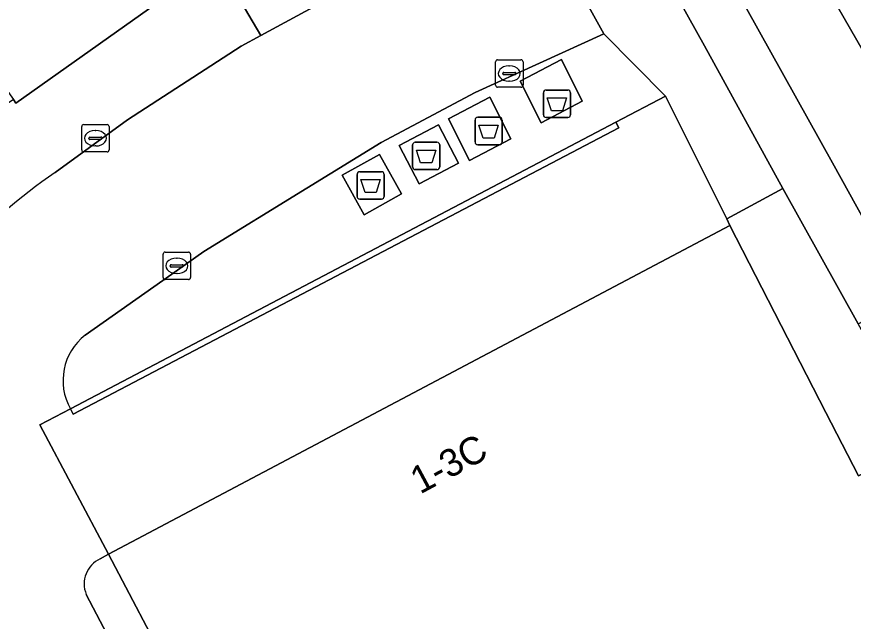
# Model space of a CAD drawing. Extents: x 161838 to 162344, y 381620 to 382160.
# Drawn here: x 162027.79 to 162058.3, y 381957.42 to 381979.46 of the extents above; entities that cross this region are included whole.
import ezdxf

# ---------------------------------------------------------------- set-up
doc = ezdxf.new("R2010")
doc.units = 0
for name, color, linetype in [('IMGEO_Afval_apart_plaats', 7, 'Continuous'), ('IMGEO_Erf', 7, 'Continuous'), ('IMGEO_Kolk', 7, 'Continuous'), ('IMGEO_Pand', 7, 'Continuous'), ('IMGEO_Pand_nummerreeks', 7, 'Continuous'), ('IMGEO_Pand_overbouw', 7, 'Continuous'), ('IMGEO_Parkeervlak_open', 7, 'Continuous'), ('IMGEO_Rijbaan_lokaal_gesloten', 7, 'Continuous'), ('IMGEO_Rijbaan_lokaal_open', 7, 'Continuous'), ('IMGEO_Voetpad_gesloten', 7, 'Continuous'), ('IMGEO_Voetpad_open', 7, 'Continuous')]:
    doc.layers.add(name, color=color, linetype=linetype)

msp = doc.modelspace()

# ---------------------------------------------------------------- linework, layer by layer
at = {"layer": 'IMGEO_Afval_apart_plaats'}
for p, q in [((162046.998, 381975.889), (162046.998, 381976.689)), ((162046.998, 381976.689), (162046.998, 381975.889)), ((162047.098, 381976.789), (162047.888, 381976.789)), ((162047.888, 381976.789), (162047.098, 381976.789)), ((162047.988, 381976.689), (162047.988, 381975.889)), ((162047.988, 381975.889), (162047.988, 381976.689)), ((162044.606, 381975.797), (162045.396, 381975.797)), ((162045.396, 381975.797), (162044.606, 381975.797)), ((162047.888, 381975.789), (162047.098, 381975.789)), ((162047.098, 381975.789), (162047.888, 381975.789)), ((162044.506, 381974.897), (162044.506, 381975.697)), ((162044.506, 381975.697), (162044.506, 381974.897)), ((162045.496, 381975.697), (162045.496, 381974.897)), ((162045.496, 381974.897), (162045.496, 381975.697)), ((162042.328, 381974.887), (162043.118, 381974.887)), ((162043.118, 381974.887), (162042.328, 381974.887)), ((162042.228, 381973.987), (162042.228, 381974.787)), ((162042.228, 381974.787), (162042.228, 381973.987)), ((162043.218, 381974.787), (162043.218, 381973.987)), ((162043.218, 381973.987), (162043.218, 381974.787)), ((162045.396, 381974.797), (162044.606, 381974.797)), ((162044.606, 381974.797), (162045.396, 381974.797)), ((162040.201, 381972.913), (162040.201, 381973.713)), ((162040.201, 381973.713), (162040.201, 381972.913)), ((162040.301, 381973.813), (162041.091, 381973.813)), ((162041.091, 381973.813), (162040.301, 381973.813)), ((162041.191, 381973.713), (162041.191, 381972.913)), ((162041.191, 381972.913), (162041.191, 381973.713)), ((162043.118, 381973.887), (162042.328, 381973.887)), ((162042.328, 381973.887), (162043.118, 381973.887)), ((162041.091, 381972.813), (162040.301, 381972.813)), ((162040.301, 381972.813), (162041.091, 381972.813))]:
    msp.add_line(p, q, dxfattribs=at)
for points in [[(162047.141, 381976.503), (162047.845, 381976.503), (162047.696, 381976.033), (162047.29, 381976.033), (162047.141, 381976.503)], [(162044.649, 381975.511), (162045.353, 381975.511), (162045.204, 381975.041), (162044.798, 381975.041), (162044.649, 381975.511)], [(162042.371, 381974.601), (162043.075, 381974.601), (162042.926, 381974.131), (162042.52, 381974.131), (162042.371, 381974.601)], [(162040.344, 381973.527), (162041.048, 381973.527), (162040.899, 381973.057), (162040.493, 381973.057), (162040.344, 381973.527)]]:
    msp.add_lwpolyline(points, dxfattribs=at)
for centre, start, end in [((162047.098, 381976.689), 90, 180), ((162047.098, 381976.689), 90, 180), ((162047.888, 381976.689), 0, 90), ((162047.888, 381976.689), 360, 90), ((162044.606, 381975.697), 90, 180), ((162044.606, 381975.697), 90, 180), ((162045.396, 381975.697), 0, 90), ((162045.396, 381975.697), 360, 90), ((162047.098, 381975.889), 180, 270), ((162047.098, 381975.889), 180, 270), ((162047.888, 381975.889), 270, 0), ((162047.888, 381975.889), 270, 0), ((162042.328, 381974.787), 90, 180), ((162042.328, 381974.787), 90, 180), ((162043.118, 381974.787), 0, 90), ((162043.118, 381974.787), 360, 90), ((162044.606, 381974.897), 180, 270), ((162044.606, 381974.897), 180, 270), ((162045.396, 381974.897), 270, 0), ((162045.396, 381974.897), 270, 0), ((162042.328, 381973.987), 180, 270), ((162042.328, 381973.987), 180, 270), ((162043.118, 381973.987), 270, 0), ((162043.118, 381973.987), 270, 0), ((162040.301, 381973.713), 90, 180), ((162040.301, 381973.713), 90, 180), ((162041.091, 381973.713), 0, 90), ((162041.091, 381973.713), 360, 90), ((162040.301, 381972.913), 180, 270), ((162040.301, 381972.913), 180, 270), ((162041.091, 381972.913), 270, 0), ((162041.091, 381972.913), 270, 0)]:
    msp.add_arc(centre, 0.1, start, end, dxfattribs=at)
at = {"layer": 'IMGEO_Erf'}
msp.add_lwpolyline([(162053.805, 381971.851), (162053.684, 381972.093), (162051.451, 381976.567), (162049.641, 381975.615), (162049.748, 381975.411), (162029.848, 381964.977), (162029.747, 381965.17), (162028.637, 381964.588), (162031.141, 381959.872)], close=True, dxfattribs=at)
at = {"layer": 'IMGEO_Kolk'}
for p, q in [((162045.33, 381977.892), (162046.182, 381977.892)), ((162045.255, 381976.966), (162045.255, 381977.818)), ((162045.743, 381977.672), (162045.768, 381977.672)), ((162046.256, 381977.818), (162046.256, 381976.966)), ((162045.514, 381977.386), (162045.514, 381977.398)), ((162045.952, 381977.349), (162045.554, 381977.349)), ((162045.557, 381977.435), (162045.955, 381977.435)), ((162045.998, 381977.398), (162045.998, 381977.386)), ((162045.766, 381977.112), (162045.741, 381977.112)), ((162046.182, 381976.892), (162045.33, 381976.892)), ((162030.159, 381974.606), (162030.159, 381975.458)), ((162030.234, 381975.532), (162031.086, 381975.532)), ((162031.16, 381975.458), (162031.16, 381974.606)), ((162030.647, 381975.312), (162030.672, 381975.312)), ((162030.418, 381975.026), (162030.418, 381975.038)), ((162030.856, 381974.989), (162030.458, 381974.989)), ((162030.461, 381975.075), (162030.859, 381975.075)), ((162030.902, 381975.038), (162030.902, 381975.026)), ((162030.67, 381974.752), (162030.645, 381974.752)), ((162031.086, 381974.532), (162030.234, 381974.532)), ((162033.202, 381970.879), (162034.054, 381970.879)), ((162033.127, 381969.953), (162033.127, 381970.805)), ((162033.615, 381970.659), (162033.64, 381970.659)), ((162034.128, 381970.805), (162034.128, 381969.953)), ((162033.386, 381970.373), (162033.386, 381970.385)), ((162033.824, 381970.336), (162033.426, 381970.336)), ((162033.429, 381970.422), (162033.827, 381970.422)), ((162033.87, 381970.385), (162033.87, 381970.373)), ((162033.638, 381970.099), (162033.613, 381970.099)), ((162034.054, 381969.879), (162033.202, 381969.879))]:
    msp.add_line(p, q, dxfattribs=at)
for points in [[(162045.33, 381977.892), (162046.182, 381977.892)], [(162045.255, 381976.966), (162045.255, 381977.818)], [(162046.256, 381977.818), (162046.256, 381976.966)], [(162046.182, 381976.892), (162045.33, 381976.892)], [(162030.159, 381974.606), (162030.159, 381975.458)], [(162030.234, 381975.532), (162031.086, 381975.532)], [(162031.16, 381975.458), (162031.16, 381974.606)], [(162031.086, 381974.532), (162030.234, 381974.532)], [(162033.202, 381970.879), (162034.054, 381970.879)], [(162033.127, 381969.953), (162033.127, 381970.805)], [(162034.128, 381970.805), (162034.128, 381969.953)], [(162034.054, 381969.879), (162033.202, 381969.879)]]:
    msp.add_lwpolyline(points, dxfattribs=at)
for centre, radius, start, end in [((162045.332, 381977.816), 0.0765, 91.552, 178.448), ((162045.332, 381977.816), 0.0765, 91.552, 178.448), ((162046.18, 381977.816), 0.0765, 1.552, 88.448), ((162046.18, 381977.816), 0.0765, 1.552, 88.448), ((162045.554, 381977.395), 0.0403, 85.8775, 175.7526), ((162045.551, 381977.385), 0.0366, 178.938, 274.7102), ((162045.955, 381977.392), 0.043, 264.8664, 352.4533), ((162045.959, 381977.397), 0.0386, 1.7309, 96.639), ((162045.332, 381976.968), 0.0765, 181.552, 268.448), ((162045.332, 381976.968), 0.0765, 181.552, 268.448), ((162046.18, 381976.968), 0.0765, 271.552, 358.448), ((162046.18, 381976.968), 0.0765, 271.552, 358.448), ((162030.236, 381975.456), 0.0765, 91.552, 178.448), ((162030.236, 381975.456), 0.0765, 91.552, 178.448), ((162031.084, 381975.456), 0.0765, 1.552, 88.448), ((162031.084, 381975.456), 0.0765, 1.552, 88.448), ((162030.458, 381975.035), 0.0403, 85.8775, 175.7526), ((162030.455, 381975.025), 0.0366, 178.938, 274.7102), ((162030.859, 381975.032), 0.043, 264.8664, 352.4533), ((162030.863, 381975.037), 0.0386, 1.7309, 96.639), ((162030.236, 381974.608), 0.0765, 181.552, 268.448), ((162030.236, 381974.608), 0.0765, 181.552, 268.448), ((162031.084, 381974.608), 0.0765, 271.552, 358.448), ((162031.084, 381974.608), 0.0765, 271.552, 358.448), ((162033.204, 381970.803), 0.0765, 91.552, 178.448), ((162033.204, 381970.803), 0.0765, 91.552, 178.448), ((162034.052, 381970.803), 0.0765, 1.552, 88.448), ((162034.052, 381970.803), 0.0765, 1.552, 88.448), ((162033.426, 381970.382), 0.0403, 85.8775, 175.7526), ((162033.423, 381970.372), 0.0366, 178.938, 274.7102), ((162033.827, 381970.379), 0.043, 264.8664, 352.4533), ((162033.831, 381970.384), 0.0386, 1.7309, 96.639), ((162033.204, 381969.955), 0.0765, 181.552, 268.448), ((162033.204, 381969.955), 0.0765, 181.552, 268.448), ((162034.052, 381969.955), 0.0765, 271.552, 358.448), ((162034.052, 381969.955), 0.0765, 271.552, 358.448)]:
    msp.add_arc(centre, radius, start, end, dxfattribs=at)
for centre, major_axis, ratio, start_param, end_param in [((162045.742, 381977.392), (-0.387, 0.002), 0.722429, 4.712389, 7.853982), ((162045.767, 381977.392), (-0.39, 0.002), 0.717154, 1.570796, 4.712389), ((162030.646, 381975.032), (-0.387, 0.002), 0.722429, 4.712389, 7.853982), ((162030.671, 381975.032), (-0.39, 0.002), 0.717154, 1.570796, 4.712389), ((162033.614, 381970.379), (-0.387, 0.002), 0.722429, 4.712389, 7.853982), ((162033.639, 381970.379), (-0.39, 0.002), 0.717154, 1.570796, 4.712389)]:
    msp.add_ellipse(centre, major_axis=major_axis, ratio=ratio, start_param=start_param, end_param=end_param, dxfattribs=at)
at = {"layer": 'IMGEO_Pand'}
for points in [[(162040.582, 381994.632), (162028.222, 381985.965), (162028.031, 381986.231), (162023.191, 381982.763), (162027.675, 381976.439), (162027.763, 381976.315), (162044.198, 381987.972), (162044.947, 381988.503), (162043.64, 381990.335), (162043.453, 381990.598)], [(162049.641, 381975.615), (162029.747, 381965.17), (162029.848, 381964.977), (162049.748, 381975.411)], [(162044.575, 381936.811), (162053.987, 381941.913), (162054.069, 381941.748), (162066.371, 381947.822), (162062.347, 381955.3), (162062.507, 381955.382), (162058.681, 381962.82), (162058.486, 381962.719), (162057.297, 381965.039), (162053.805, 381971.851), (162031.141, 381959.872), (162033.406, 381955.541), (162034.815, 381952.864), (162035.005, 381952.503), (162034.793, 381952.391), (162043.321, 381936.152)]]:
    msp.add_lwpolyline(points, close=True, dxfattribs=at)
at = {"layer": 'IMGEO_Pand_overbouw'}
msp.add_lwpolyline([(162049.641, 381975.615), (162049.748, 381975.411), (162029.848, 381964.977), (162029.747, 381965.17), (162028.637, 381964.588), (162031.141, 381959.872), (162053.805, 381971.851), (162053.684, 381972.093), (162051.451, 381976.567)], close=True, dxfattribs=at)
at = {"layer": 'IMGEO_Parkeervlak_open'}
msp.add_lwpolyline([(162040.218, 381980.693), (162041.531, 381981.323), (162040.709, 381982.892), (162035.821, 381980.27), (162036.696, 381978.775)], close=True, dxfattribs=at)
at = {"layer": 'IMGEO_Rijbaan_lokaal_gesloten'}
msp.add_lwpolyline([(162052.156, 381989.515), (162059.541, 381976.691), (162060.183, 381975.633), (162062.982, 381970.801), (162063.362, 381970.116), (162074.557, 381949.731), (162075.351, 381948.25), (162082.607, 381935.111), (162083.793, 381932.952), (162085.682, 381929.519), (162092.687, 381916.789), (162101.169, 381901.585), (162104.943, 381895.096), (162107.401, 381891.02), (162110.364, 381886.414)], dxfattribs=at)
at = {"layer": 'IMGEO_Rijbaan_lokaal_open'}
for points in [[(162030.285, 381967.852), (162033.449, 381970.08), (162034.611, 381970.899), (162038.368, 381973.216), (162041.076, 381974.876), (162044.515, 381976.696), (162049.208, 381978.843), (162046.895, 381983.013), (162046.506, 381983.71), (162041.531, 381981.323), (162040.218, 381980.693), (162036.696, 381978.775), (162035.979, 381978.385), (162031.836, 381975.698), (162029.188, 381973.784)], [(162030.835, 381959.696), (162031.141, 381959.872), (162028.637, 381964.588), (162029.747, 381965.17)], [(162031.719, 381955.736), (162030.327, 381958.403)]]:
    msp.add_lwpolyline(points, dxfattribs=at)
for centre, radius, start, end in [((162042.038, 381955.244), 22.558, 124.7269, 136.5982), ((162031.576, 381966.198), 2.098, 127.9815, 209.3329), ((162031.241, 381958.79), 0.993, 114.1368, 202.965)]:
    msp.add_arc(centre, radius, start, end, dxfattribs=at)
at = {"layer": 'IMGEO_Voetpad_gesloten'}
for points in [[(162047.659, 381977.906), (162046.154, 381977.114), (162046.912, 381975.592), (162048.417, 381976.384)], [(162045.047, 381976.532), (162043.542, 381975.74), (162044.301, 381974.218), (162045.806, 381975.01)], [(162043.172, 381975.525), (162041.738, 381974.772), (162042.471, 381973.374), (162043.906, 381974.126)], [(162041.019, 381974.44), (162039.655, 381973.681), (162040.456, 381972.243), (162041.82, 381973.002)]]:
    msp.add_lwpolyline(points, close=True, dxfattribs=at)
at = {"layer": 'IMGEO_Voetpad_open'}
for points in [[(162052.156, 381989.515), (162050.487, 381992.336), (162047.488, 381991.618), (162049.912, 381987.839), (162057.538, 381974.132), (162060.262, 381969.214), (162061.99, 381970.222), (162062.982, 381970.801), (162060.183, 381975.633), (162059.541, 381976.691)], [(162049.483, 381984.485), (162047.552, 381988.022), (162045.575, 381991.113), (162043.453, 381990.598), (162043.64, 381990.335), (162044.947, 381988.503), (162044.198, 381987.972), (162046.506, 381983.71), (162046.895, 381983.013), (162049.208, 381978.843), (162051.451, 381976.567), (162053.684, 381972.093), (162055.738, 381973.205), (162052.869, 381978.398)], [(162046.912, 381975.592), (162046.154, 381977.114), (162047.659, 381977.906), (162048.417, 381976.384)], [(162045.806, 381975.01), (162044.301, 381974.218), (162043.542, 381975.74), (162045.047, 381976.532)], [(162043.906, 381974.126), (162042.471, 381973.374), (162041.738, 381974.772), (162043.172, 381975.525)], [(162041.82, 381973.002), (162040.456, 381972.243), (162039.655, 381973.681), (162041.019, 381974.44)]]:
    msp.add_lwpolyline(points, close=True, dxfattribs=at)
for points in [[(162044.198, 381987.972), (162027.763, 381976.315), (162027.675, 381976.439), (162023.633, 381973.703), (162017.37, 381969.238), (162016.075, 381968.353), (162010.268, 381964.214), (162004.459, 381960.074), (162003.552, 381959.398), (161999.988, 381956.857), (161997.98, 381955.381), (161997.314, 381955), (161991.394, 381951.62), (161990.45, 381950.969), (161985.242, 381948.014), (161980.473, 381945.309), (161975.721, 381942.613), (161974.954, 381942.172), (161969.673, 381939.049), (161967.538, 381937.787), (161959.912, 381939.177), (161958.703, 381939.397), (161937.628, 381943.237), (161912.446, 381947.826)], [(162049.483, 381984.485), (162052.869, 381978.398), (162055.738, 381973.205), (162058.476, 381968.271), (162060.262, 381969.214), (162057.538, 381974.132), (162049.912, 381987.839)], [(162029.188, 381973.784), (162031.836, 381975.698), (162035.979, 381978.385), (162036.696, 381978.775), (162035.821, 381980.27)], [(162051.451, 381976.567), (162049.208, 381978.843), (162044.515, 381976.696), (162041.076, 381974.876), (162038.368, 381973.216), (162034.611, 381970.899), (162033.449, 381970.08), (162030.285, 381967.852)], [(162029.747, 381965.17), (162049.641, 381975.615), (162051.451, 381976.567)], [(162102.392, 381889.138), (162058.476, 381968.271), (162055.738, 381973.205), (162053.684, 381972.093), (162053.805, 381971.851), (162057.297, 381965.039), (162058.486, 381962.719), (162058.681, 381962.82), (162062.507, 381955.382), (162062.347, 381955.3), (162066.371, 381947.822), (162069.509, 381941.843), (162074.751, 381932.689), (162075.894, 381930.692), (162084.904, 381914.958)], [(162033.051, 381955.344), (162033.406, 381955.541), (162031.141, 381959.872), (162030.835, 381959.696)], [(162030.327, 381958.403), (162031.719, 381955.736)]]:
    msp.add_lwpolyline(points, dxfattribs=at)
for centre, radius, start, end in [((162042.038, 381955.244), 22.558, 124.7269, 136.5982), ((162031.576, 381966.198), 2.098, 127.9815, 209.3329), ((162031.241, 381958.79), 0.993, 114.1368, 202.965)]:
    msp.add_arc(centre, radius, start, end, dxfattribs=at)

# ---------------------------------------------------------------- texts
at = {"layer": 'IMGEO_Pand_nummerreeks'}
msp.add_text('1-3C', height=1, rotation=28.2729, dxfattribs=at).set_placement((162042.5, 381962.038))

doc.saveas('drawing.dxf')
